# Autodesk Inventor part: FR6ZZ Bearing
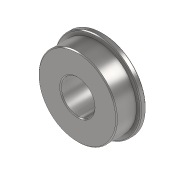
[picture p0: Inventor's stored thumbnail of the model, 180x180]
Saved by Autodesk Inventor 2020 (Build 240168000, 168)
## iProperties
Created: 2020-01
Part Number: FR6ZZ Bearing
Material: Steel, Carbon
Document SubType Name: Modeling
Designer: woodk
Density: 7.85 g/cm^3
Appearance: Semi-Polished
Vendor: KoP
Mass: 18.821 g
Surface Area: 14.9874 cm^2
Volume: 2.39758 cm^3
Author: woodk
Revision Number: ANY
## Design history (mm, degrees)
feature "Imported1"
body "Solid1"
